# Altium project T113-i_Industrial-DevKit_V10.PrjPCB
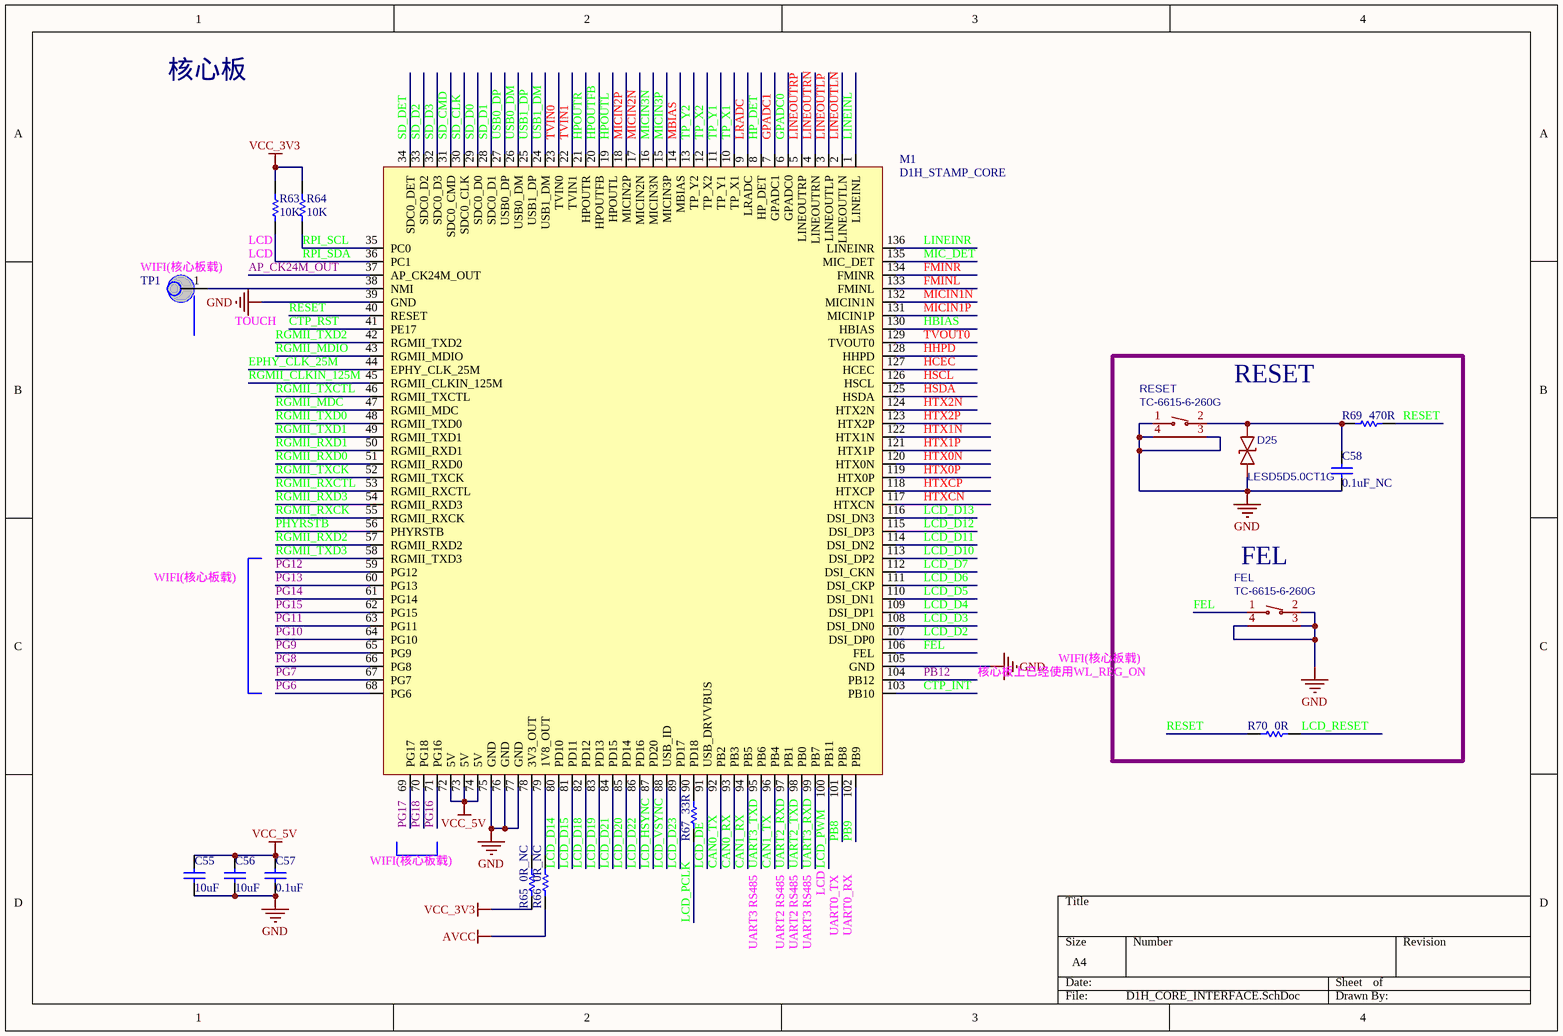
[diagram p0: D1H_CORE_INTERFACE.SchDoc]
6 sheets, 249 parts. Net scope: global (net labels, ports and power ports of the same name join across sheets).
Board file: T113-i_Industrial-DevKit_V10.PcbDoc
Sheets:
  D1H_CORE_INTERFACE.SchDoc
  AUDIO&KEY&EXPAND_IO.SchDoc
  USB&TF.SchDoc
  LCD&PWR.SchDoc
  ETHERNET.SchDoc
  RS485&CAN.SchDoc

## Sheet D1H_CORE_INTERFACE.SchDoc
size A4

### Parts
C55  10uF  [0402]
C56  10uF  [0402]
C57  0.1uF  [0402]
C58  0.1uF_NC  [0402]
D25  LESD5D5.0CT1G  [SOD-523_L1.2-W0.8-LS1.6-BI]
FEL  TC-6615-6-260G  [KEY-TH_TC-6615-6-160G]
M1  D1H_STAMP_CORE  [D1H_STAMP_CORE]
R63  10K  [0402]
R64  10K  [0402]
R65  0R_NC  [1206R]
R66  0R_NC  [1206R]
R67  33R  [0402]
R69  470R  [0402]
R70  0R  [0402]
RESET  TC-6615-6-260G  [KEY-TH_TC-6615-6-160G]
TP1  (no value)  [TP_1MM]

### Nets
AVCC: R66.2
GND: C55.1 C56.1 C57.1 C58.2 D25.1 FEL.2 FEL.3 FEL.4 M1.39(GND) M1.75(GND) M1.76(GND) M1.77(GND) M1.105(GND) RESET.1 RESET.3 RESET.4
VCC_3V3: R63.2 R64.2 R65.2  [project net VCC33_EPHY]
VCC_5V: C55.2 C56.2 C57.2 M1.72(5V) M1.73(5V) M1.74(5V)
AP_CK24M_OUT: M1.37(AP_CK24M_OUT)
CAN0_RX: M1.93(PB3)
CAN0_TX: M1.92(PB2)
CAN1_RX: M1.94(PB5)
CAN1_TX: M1.96(PB4)
CTP_INT: M1.103(PB10)
CTP_RST: M1.41(PE17)
EPHY_CLK_25M: M1.44(EPHY_CLK_25M)
FEL: FEL.1 M1.106(FEL)
FMINL: M1.133(FMINL)
FMINR: M1.134(FMINR)
GPADC0: M1.6(GPADC0)
GPADC1: M1.7(GPADC1)
HBIAS: M1.130(HBIAS)
HCEC: M1.127(HCEC)
HHPD: M1.128(HHPD)
HP_DET: M1.8(HP_DET)
HPOUTFB: M1.20(HPOUTFB)
HPOUTL: M1.19(HPOUTL)
HPOUTR: M1.21(HPOUTR)
HSCL: M1.126(HSCL)
HSDA: M1.125(HSDA)
HTX0N: M1.120(HTX0N)
HTX0P: M1.119(HTX0P)
HTX1N: M1.122(HTX1N)
HTX1P: M1.121(HTX1P)
HTX2N: M1.124(HTX2N)
HTX2P: M1.123(HTX2P)
HTXCN: M1.117(HTXCN)
HTXCP: M1.118(HTXCP)
LCD_D2: M1.107(DSI_DP0)
LCD_D3: M1.108(DSI_DN0)
LCD_D4: M1.109(DSI_DP1)
LCD_D5: M1.110(DSI_DN1)
LCD_D6: M1.111(DSI_CKP)
LCD_D7: M1.112(DSI_CKN)
LCD_D10: M1.113(DSI_DP2)
LCD_D11: M1.114(DSI_DN2)
LCD_D12: M1.115(DSI_DP3)
LCD_D13: M1.116(DSI_DN3)
LCD_D14: M1.80(PD10)
LCD_D15: M1.81(PD11)
LCD_D18: M1.82(PD12)
LCD_D19: M1.83(PD13)
LCD_D20: M1.85(PD14)
LCD_D21: M1.84(PD15)
LCD_D22: M1.86(PD16)
LCD_D23: M1.89(PD17)
LCD_DE: M1.91(USB_DRVVBUS)
LCD_HSYNC: M1.87(PD20)
LCD_PCLK: R67.1
LCD_PWM: M1.100(PB11)
LCD_RESET: R70.2
LCD_VSYNC: M1.88(USB_ID)
LINEINL: M1.1(LINEINL)
LINEINR: M1.136(LINEINR)
LINEOUTLN: M1.2(LINEOUTLN)
LINEOUTLP: M1.3(LINEOUTLP)
LINEOUTRN: M1.4(LINEOUTRN)
LINEOUTRP: M1.5(LINEOUTRP)
LRADC: M1.9(LRADC)
MBIAS: M1.14(MBIAS)
MIC_DET: M1.135(MIC_DET)
MICIN1N: M1.132(MICIN1N)
MICIN1P: M1.131(MICIN1P)
MICIN2N: M1.17(MICIN2N)
MICIN2P: M1.18(MICIN2P)
MICIN3N: M1.16(MICIN3N)
MICIN3P: M1.15(MICIN3P)
PB8: M1.101(PB8)
PB9: M1.102(PB9)
PB12: M1.104(PB12)
PG6: M1.68(PG6)
PG7: M1.67(PG7)
PG8: M1.66(PG8)
PG9: M1.65(PG9)
PG10: M1.64(PG10)
PG11: M1.63(PG11)
PG12: M1.59(PG12)
PG13: M1.60(PG13)
PG14: M1.61(PG14)
PG15: M1.62(PG15)
PG16: M1.71(PG16)
PG17: M1.69(PG17)
PG18: M1.70(PG18)
PHYRSTB: M1.56(PHYRSTB)
RESET: M1.40(RESET) R69.2 R70.1
RGMII_CLKIN_125M: M1.45(RGMII_CLKIN_125M)
RGMII_MDC: M1.47(RGMII_MDC)
RGMII_MDIO: M1.43(RGMII_MDIO)
RGMII_RXCK: M1.55(RGMII_RXCK)
RGMII_RXCTL: M1.53(RGMII_RXCTL)
RGMII_RXD0: M1.51(RGMII_RXD0)
RGMII_RXD1: M1.50(RGMII_RXD1)
RGMII_RXD2: M1.57(RGMII_RXD2)
RGMII_RXD3: M1.54(RGMII_RXD3)
RGMII_TXCK: M1.52(RGMII_TXCK)
RGMII_TXCTL: M1.46(RGMII_TXCTL)
RGMII_TXD0: M1.48(RGMII_TXD0)
RGMII_TXD1: M1.49(RGMII_TXD1)
RGMII_TXD2: M1.42(RGMII_TXD2)
RGMII_TXD3: M1.58(RGMII_TXD3)
RPI_SCL: M1.35(PC0) R64.1
RPI_SDA: M1.36(PC1) R63.1
SD_CLK: M1.30(SDC0_CLK)
SD_CMD: M1.31(SDC0_CMD)
SD_D0: M1.29(SDC0_D0)
SD_D1: M1.28(SDC0_D1)
SD_D2: M1.33(SDC0_D2)
SD_D3: M1.32(SDC0_D3)
SD_DET: M1.34(SDC0_DET)
TP_X1: M1.10(TP_X1)
TP_X2: M1.12(TP_X2)
TP_Y1: M1.11(TP_Y1)
TP_Y2: M1.13(TP_Y2)
TVIN0: M1.23(TVIN0)
TVIN1: M1.22(TVIN1)
TVOUT0: M1.129(TVOUT0)
UART2_RXD: M1.97(PB1)
UART2_TXD: M1.98(PB0)
UART3_RXD: M1.99(PB7)
UART3_TXD: M1.95(PB6)
USB0_DM: M1.26(USB0_DM)
USB0_DP: M1.27(USB0_DP)
USB1_DM: M1.24(USB1_DM)
USB1_DP: M1.25(USB1_DP)
NetC58_1: C58.1 D25.2 R69.1 RESET.2
NetM1_38: M1.38(NMI) TP1.1
NetM1_78: M1.78(3V3_OUT) R65.1
NetM1_79: M1.79(1V8_OUT) R66.1
NetM1_90: M1.90(PD18) R67.2

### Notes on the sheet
- 核心板
- (near R63) LCD
- (near TP1) WIFI(核心板载)
- LCD
- TOUCH
- RESET
- WIFI(核心板载)
- (near FEL) FEL
- 核心板上已经使用WL_REG_ON
- UART3 RS485
- UART2 RS485
- UART0_TX
- UART0_RX

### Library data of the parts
C55-C58 = Cap: Capacitor; PartNumber: CAP100NF
D25 = LESD5D5.0CT1G: BOM_Manufacturer: Leshan Radio; Contributor: LCSC
FEL RESET = TC-6615-6-260G: Contributor: LCSC
R63 R64 R67 R69 R70 = Res1: Resistor; PartNumber: RES2.2K
R65 R66 = Res1: Resistor; PartNumber: RES22R
TP1 = TP

## Sheet AUDIO&KEY&EXPAND_IO.SchDoc
size A4; PageSetup: Record=PageOptions|CenterHorizontal=True|CenterVertical=True|PrintScale=0.50|XCorrection=1.00|YCorrection=1.00|PrintKind=1|BorderSize=5000000|LeftOffset=0|BottomOffset=0|Orientation=2|PaperLength=1000|PaperWidth=1000|Scale=100|PaperSource=7|PrintQuality=-4|MediaType=1|DitherType=10|PaperKind=A4|PrintScaleMode=1
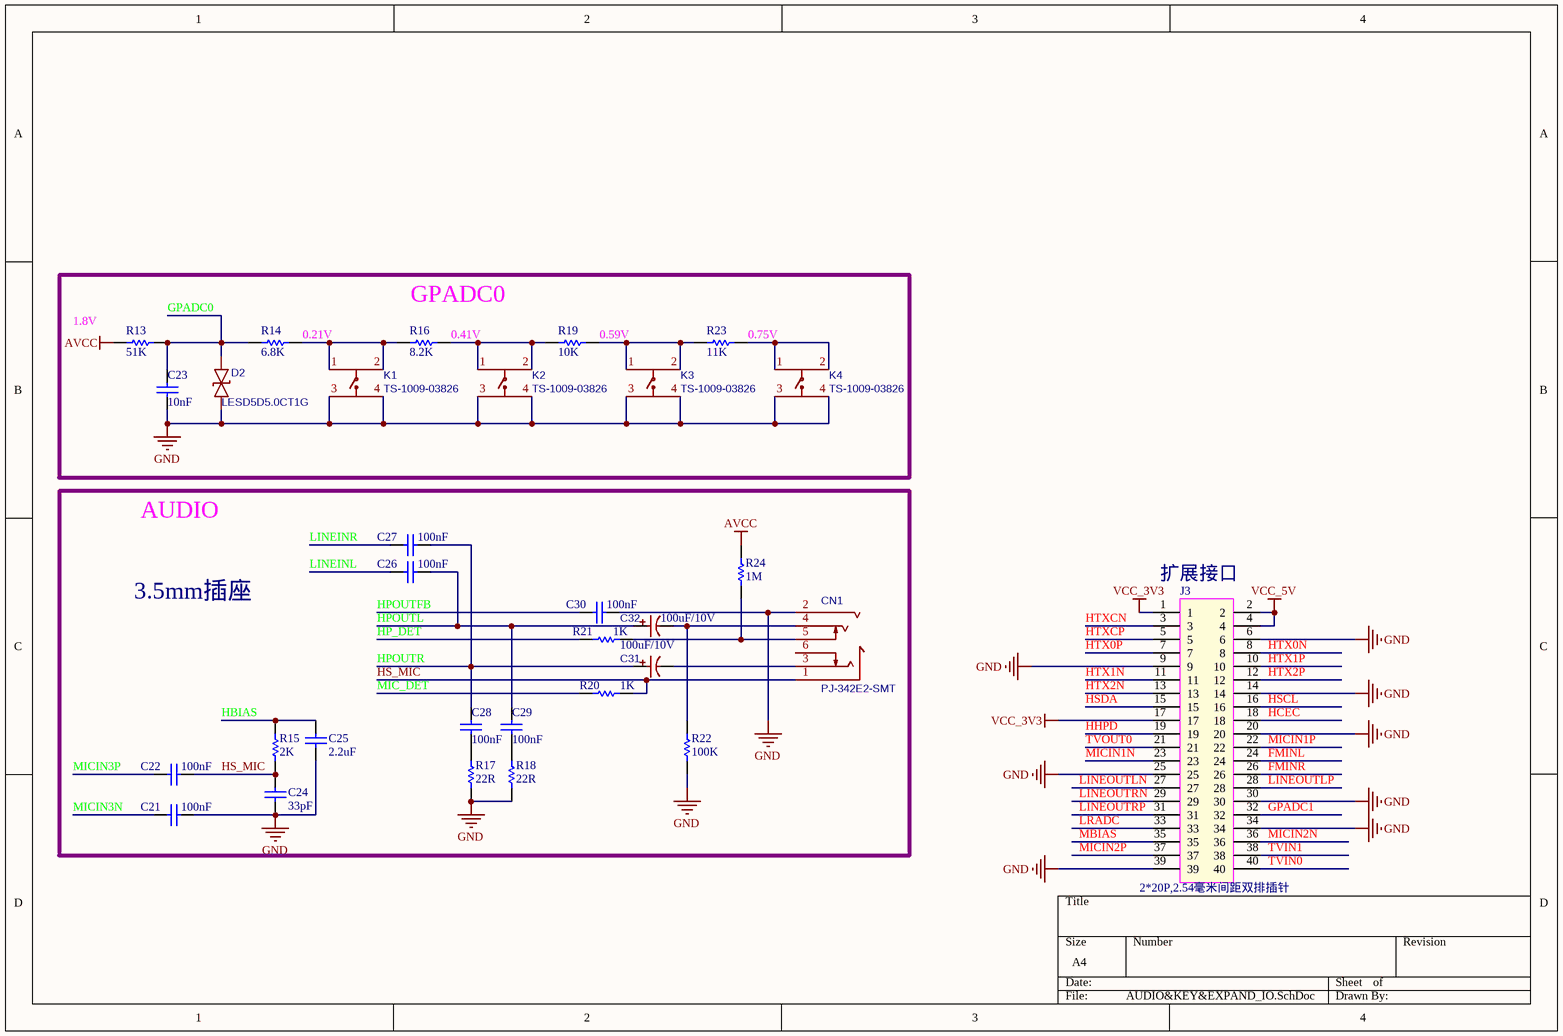
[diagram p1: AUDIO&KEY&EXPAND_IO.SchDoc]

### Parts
C21  100nF  [0402]
C22  100nF  [0402]
C23  10nF  [0402]
C24  33pF  [0402]
C25  2.2uF  [0402]
C26  100nF  [0402]
C27  100nF  [0402]
C28  100nF  [0402]
C29  100nF  [0402]
C30  100nF  [0402]
C31  100uF/10V  [CAP-SMD_CASE_B]
C32  100uF/10V  [CAP-SMD_CASE_B]
CN1  PJ-342E2-SMT  [AUDIO-SMD_PJ-342E2-SMT]
D2  LESD5D5.0CT1G  [SOD-523_L1.2-W0.8-LS1.6-BI]
J3  2*20P,2.54毫米间距双排插针  [HDR-SMD_40P-P2.54-V-M-R2-C20-LS7.5]
K1  TS-1009-03826  [SW-TH_4P-L4.5-W4.5-P3.00-LS5.5]
K2  TS-1009-03826  [SW-TH_4P-L4.5-W4.5-P3.00-LS5.5]
K3  TS-1009-03826  [SW-TH_4P-L4.5-W4.5-P3.00-LS5.5]
K4  TS-1009-03826  [SW-TH_4P-L4.5-W4.5-P3.00-LS5.5]
R13  51K  [0402]
R14  6.8K  [0402]
R15  2K  [0402]
R16  8.2K  [0402]
R17  22R  [0402]
R18  22R  [0402]
R19  10K  [0402]
R20  1K  [0402]
R21  1K  [0402]
R22  100K  [0402]
R23  11K  [0402]
R24  1M  [0402]

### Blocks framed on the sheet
GPADC0: C23 D2 K1-K4 R13 R14 R16 R19 R23

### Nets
AVCC: R13.2 R24.2
GND: C21.1 C23.2 C24.2 C25.2 C30.1 CN1.2 D2.1 J3.6 J3.9 J3.14 J3.20 J3.25 J3.30 J3.34 J3.39 K1.3 K1.4 K2.3 K2.4 K3.3 K3.4 K4.3 K4.4 R17.2 R18.2 R22.1
VCC_3V3: J3.1 J3.17  [project net VCC33_EPHY]
VCC_5V: J3.2 J3.4
FMINL: J3.24
FMINR: J3.26
GPADC0: C23.1 D2.2 R13.1 R14.2
GPADC1: J3.32
HBIAS: C25.1 R15.2
HCEC: J3.18
HHPD: J3.19
HP_DET: R21.2
HPOUTFB: C30.2
HPOUTL: C26.2 C29.1 C32.1
HPOUTR: C27.2 C28.1 C31.1
HS_MIC: C22.1 C24.1 CN1.1 R15.1 R20.1
HSCL: J3.16
HSDA: J3.15
HTX0N: J3.8
HTX0P: J3.7
HTX1N: J3.11
HTX1P: J3.10
HTX2N: J3.13
HTX2P: J3.12
HTXCN: J3.3
HTXCP: J3.5
LINEINL: C26.1
LINEINR: C27.1
LINEOUTLN: J3.27
LINEOUTLP: J3.28
LINEOUTRN: J3.29
LINEOUTRP: J3.31
LRADC: J3.33
MBIAS: J3.35
MIC_DET: R20.2
MICIN1N: J3.23
MICIN1P: J3.22
MICIN2N: J3.36
MICIN2P: J3.37
MICIN3N: C21.2
MICIN3P: C22.2
TVIN0: J3.40
TVIN1: J3.38
TVOUT0: J3.21
NetC28_2: C28.2 R17.1
NetC29_2: C29.2 R18.1
NetC31_2: C31.2 CN1.3
NetC32_2: C32.2 CN1.4 R22.2
NetCN1_5: CN1.5 R21.1 R24.1
NetK1_1: K1.1 K1.2 R14.1 R16.2
NetK2_1: K2.1 K2.2 R16.1 R19.2
NetK3_1: K3.1 K3.2 R19.1 R23.2
NetK4_1: K4.1 K4.2 R23.1

Not connected (* = marked no-connect by the designer): CN1 6

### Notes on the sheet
- (near R13) 1.8V
- (near R14) 0.21V
- (near R16) 0.41V
- (near R19) 0.59V
- (near R23) 0.75V
- AUDIO
- (near J3) 扩展接口
- 3.5mm插座

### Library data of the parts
C21-C30 = Cap: Capacitor; PartNumber: CAP100NF
C31 C32 = 100uF: BOM_Manufacturer: ReliaPro; nameAlias: Capacitance
CN1 = PJ-342E2-SMT: BOM_Manufacturer: XKB Connectivity; Contributor: LCSC
D2 = LESD5D5.0CT1G: as D25 on sheet D1H_CORE_INTERFACE
J3 = IDC40
K1-K4 = KEY_C174049: BOM_Manufacturer: BOOMELE(Boom Precision Elec); Contributor: LCSC; SMT Type: Extend
R13-R24 = Res1: Resistor; PartNumber: RES2.2K

## Sheet USB&TF.SchDoc
size A4
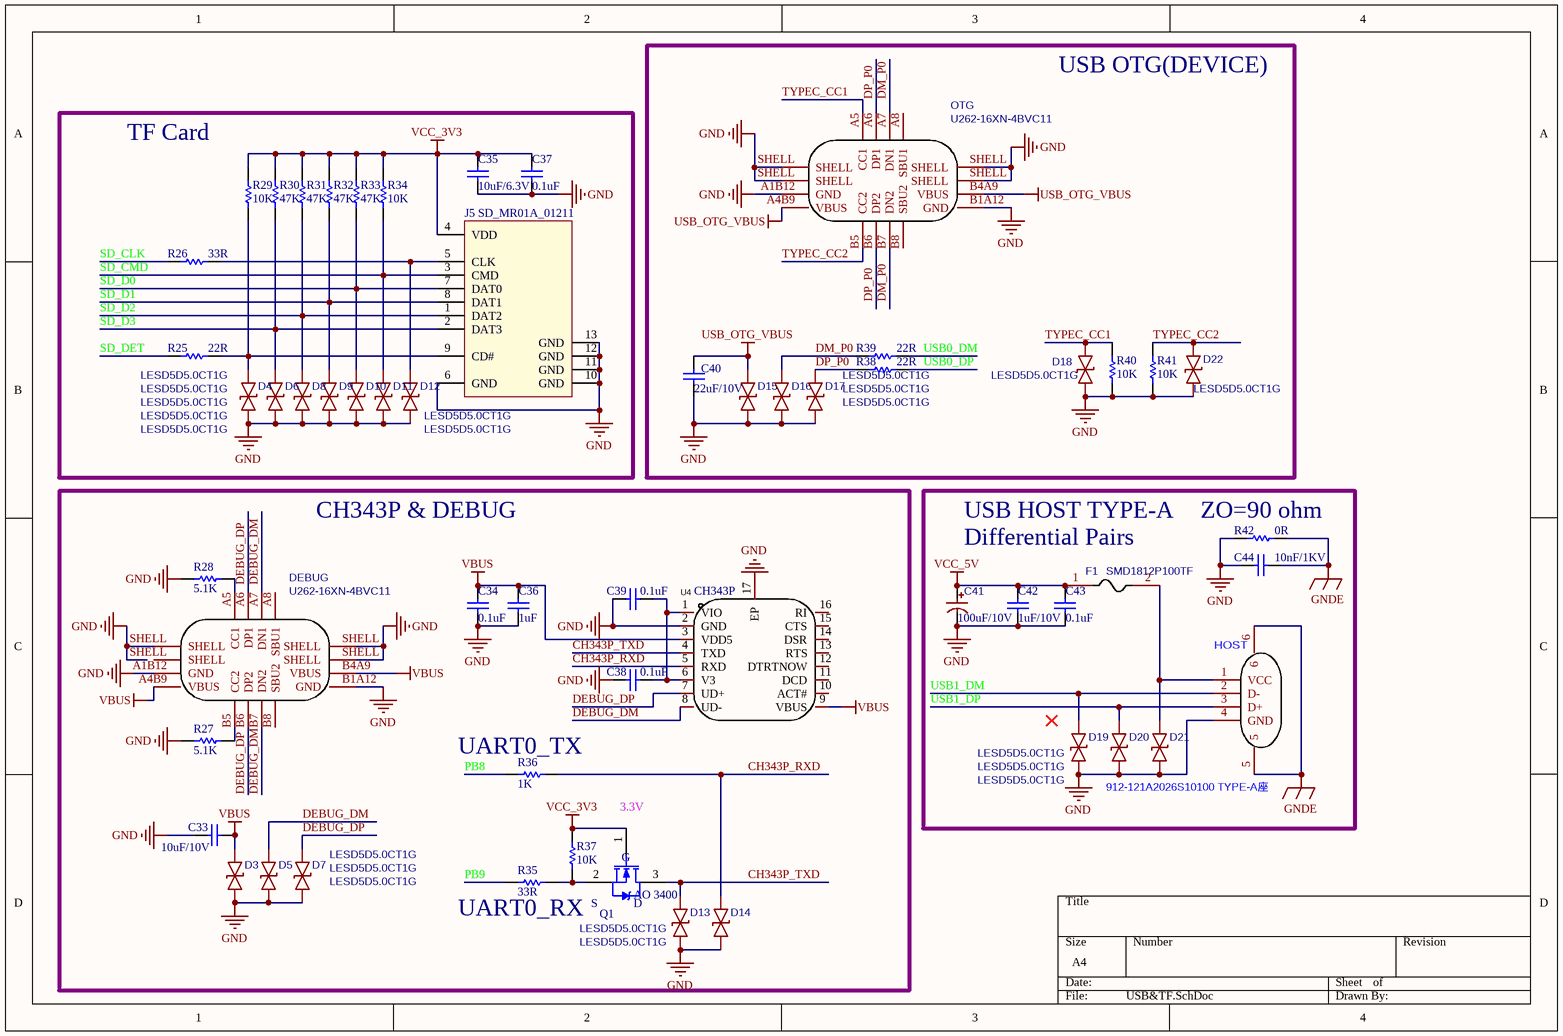
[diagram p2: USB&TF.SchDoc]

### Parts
C33  10uF/10V  [0402]
C34  0.1uF  [0402]
C35  10uF/6.3V  [0402]
C36  1uF  [0402]
C37  0.1uF  [0402]
C38  0.1uF  [0402]
C39  0.1uF  [0402]
C40  22uF/10V  [0603]
C41  100uF/10V  [CAP-SMD_CASE_B]
C42  1uF/10V  [0402]
C43  0.1uF  [0402]
C44  10nF/1KV  [1206C]
D3  LESD5D5.0CT1G  [SOD-523_L1.2-W0.8-LS1.6-BI]
D4  LESD5D5.0CT1G  [SOD-523_L1.2-W0.8-LS1.6-BI]
D5  LESD5D5.0CT1G  [SOD-523_L1.2-W0.8-LS1.6-BI]
D6  LESD5D5.0CT1G  [SOD-523_L1.2-W0.8-LS1.6-BI]
D7  LESD5D5.0CT1G  [SOD-523_L1.2-W0.8-LS1.6-BI]
D8  LESD5D5.0CT1G  [SOD-523_L1.2-W0.8-LS1.6-BI]
D9  LESD5D5.0CT1G  [SOD-523_L1.2-W0.8-LS1.6-BI]
D10  LESD5D5.0CT1G  [SOD-523_L1.2-W0.8-LS1.6-BI]
D11  LESD5D5.0CT1G  [SOD-523_L1.2-W0.8-LS1.6-BI]
D12  LESD5D5.0CT1G  [SOD-523_L1.2-W0.8-LS1.6-BI]
D13  LESD5D5.0CT1G  [SOD-523_L1.2-W0.8-LS1.6-BI]
D14  LESD5D5.0CT1G  [SOD-523_L1.2-W0.8-LS1.6-BI]
D15  LESD5D5.0CT1G  [SOD-523_L1.2-W0.8-LS1.6-BI]
D16  LESD5D5.0CT1G  [SOD-523_L1.2-W0.8-LS1.6-BI]
D17  LESD5D5.0CT1G  [SOD-523_L1.2-W0.8-LS1.6-BI]
D18  LESD5D5.0CT1G  [SOD-523_L1.2-W0.8-LS1.6-BI]
D19  LESD5D5.0CT1G  [SOD-523_L1.2-W0.8-LS1.6-BI]
D20  LESD5D5.0CT1G  [SOD-523_L1.2-W0.8-LS1.6-BI]
D21  LESD5D5.0CT1G  [SOD-523_L1.2-W0.8-LS1.6-BI]
D22  LESD5D5.0CT1G  [SOD-523_L1.2-W0.8-LS1.6-BI]
DEBUG  U262-16XN-4BVC11  [TYPEC-12PIN - duplicate]
F1  SMD1812P100TF  [F1812]
HOST  912-121A2026S10100 TYPE-A座  [USB-A-TH_C42425]
J5  SD_MR01A_01211  [SD-MR01A-01211]
OTG  U262-16XN-4BVC11  [TYPEC-12PIN - duplicate]
Q1  AO 3400  [SOT23]
R25  22R  [0402]
R26  33R  [0402]
R27  5.1K  [0402]
R28  5.1K  [0402]
R29  10K  [0402]
R30  47K  [0402]
R31  47K  [0402]
R32  47K  [0402]
R33  47K  [0402]
R34  10K  [0402]
R35  33R  [0402]
R36  1K  [0402]
R37  10K  [0402]
R38  22R  [0402]
R39  22R  [0402]
R40  10K  [0402]
R41  10K  [0402]
R42  0R  [1206R]
U4  CH343P  [TQFN-16_L3.0-W3.0-P0.50-BL-EP1.7]

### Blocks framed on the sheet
USB OTG(DEVICE): C40 D15-D18 D22 OTG R38-R41
TF Card: C35 C37 D4 D6 D8-D12 J5 R25 R26 R29-R34

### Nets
GND: C33.1 C34.2 C35.2 C36.2 C37.2 C38.1 C39.1 C40.1 C41.2 C42.1 C43.2 C44.1 D3.1 D4.1 D5.1 D6.1 D7.1 D8.1 D9.1 D10.1 D11.1 D12.1 D13.2 D14.2 D15.1 D16.1 D17.1 D18.1 D19.1 D20.1 D21.1 D22.1 DEBUG.A1B12(GND) DEBUG.B1A12(GND) DEBUG.SHELL HOST.4(GND) J5.6(GND) J5.10(GND) J5.11(GND) J5.12(GND) J5.13(GND) OTG.A1B12(GND) OTG.B1A12(GND) OTG.SHELL R27.2 R28.2 R40.1 R41.1 R42.1 U4.2(GND) U4.17(EP)
GNDE: C44.2 HOST.5 HOST.6 R42.2
USB_OTG_VBUS: C40.2 D15.2 OTG.A4B9(VBUS) OTG.B4A9(VBUS)
VBUS: C33.2 C34.1 C36.1 D3.2 DEBUG.A4B9(VBUS) DEBUG.B4A9(VBUS) U4.3(VDD5) U4.9(VBUS)
VCC_3V3: C35.1 C37.1 J5.4(VDD) Q1.1(G) R29.1 R30.1 R31.1 R32.1 R33.1 R34.1 R37.1  [project net VCC33_EPHY]
VCC_5V: C41.1 C42.2 C43.1 F1.1
CH343P_RXD: D14.1 R36.2 U4.5(RXD)
CH343P_TXD: D13.1 Q1.3(D) U4.4(TXD)
DEBUG_DM: D5.2 DEBUG.A7(DN1) DEBUG.B7(DN2) U4.8(UD-)
DEBUG_DP: D7.2 DEBUG.A6(DP1) DEBUG.B6(DP2) U4.7(UD+)
DM_P0: D16.2 OTG.A7(DN1) OTG.B7(DN2) R39.1
DP_P0: D17.2 OTG.A6(DP1) OTG.B6(DP2) R38.1
PB8: R36.1
PB9: R35.1
SD_CLK: R26.2
SD_CMD: D11.2 J5.3(CMD) R34.2
SD_D0: D10.2 J5.7(DAT0) R33.2
SD_D1: D9.2 J5.8(DAT1) R32.2
SD_D2: D8.2 J5.1(DAT2) R31.2
SD_D3: D6.2 J5.2(DAT3) R30.2
SD_DET: R25.2
TYPEC_CC1: D18.2 OTG.A5(CC1) R40.2
TYPEC_CC2: D22.2 OTG.B5(CC2) R41.2
USB0_DM: R39.2
USB0_DP: R38.2
USB1_DM: D19.2 HOST.2(D-)
USB1_DP: D20.2 HOST.3(D+)
NetC38_2: C38.2 C39.2 U4.1(VIO) U4.6(V3)
NetD4_2: D4.2 J5.9(CD#) R25.1 R29.2
NetD12_2: D12.2 J5.5(CLK) R26.1
NetD21_2: D21.2 F1.2 HOST.1(VCC)
NetDEBUG_A5: DEBUG.A5(CC1) R28.1
NetDEBUG_B5: DEBUG.B5(CC2) R27.1
NetQ1_2: Q1.2(S) R35.2 R37.2

Not connected (* = marked no-connect by the designer): DEBUG A8(SBU1) B8(SBU2); OTG A8(SBU1) B8(SBU2); U4 10(ACT#) 11(DCD) 12(DTRTNOW) 13(RTS) 14(DSR) 15(CTS) 16(RI)

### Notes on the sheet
- CH343P & DEBUG
- USB HOST TYPE-A
- (near R42) ZO=90 ohm
- Differential Pairs
- (near R36) UART0_TX
- 3.3V
- (near R35) UART0_RX

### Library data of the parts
C33-C40 C42-C44 = Cap: Capacitor; PartNumber: CAP100NF
C41 = 100uF: as C31 on sheet AUDIO&KEY&EXPAND_IO
D3 D5 D7 D13-D22 = LESD5D5.0CT1G: as D25 on sheet D1H_CORE_INTERFACE
D4 D6 D8-D12 = LESD5D5.0CT1G: BOM_Manufacturer: Leshan Radio; Contributor: LCSC; BOM_Paste Type: expand
DEBUG OTG = U262-16XN-4BVC11: BOM_Manufacturer: XKB Enterprise; Contributor: LCSC
F1 = SMD1812P014TF: BOM_Manufacturer: RUILON
HOST = JTJ-USB-AF-90-10.6X13.1-H5.7-002
Q1 = 1110505011: Note: Pin 2 is electrically connected to pin 4.; 序号: 2666; 存货名称: 场效应管; 规格型号: AO3400,SOT23,N沟道; 主计量单位名称: ֻ; 安全库存: 1346; 旧编码: 010605010; 旧规格型号: N沟道 AO 3400 SOT23
R25-R37 = Res1: Resistor; PartNumber: RES2.2K
R38-R42 = Res1: Resistor; PartNumber: RES22R
U4 = CH343P: Add into BOM: yes

## Sheet LCD&PWR.SchDoc
size A4
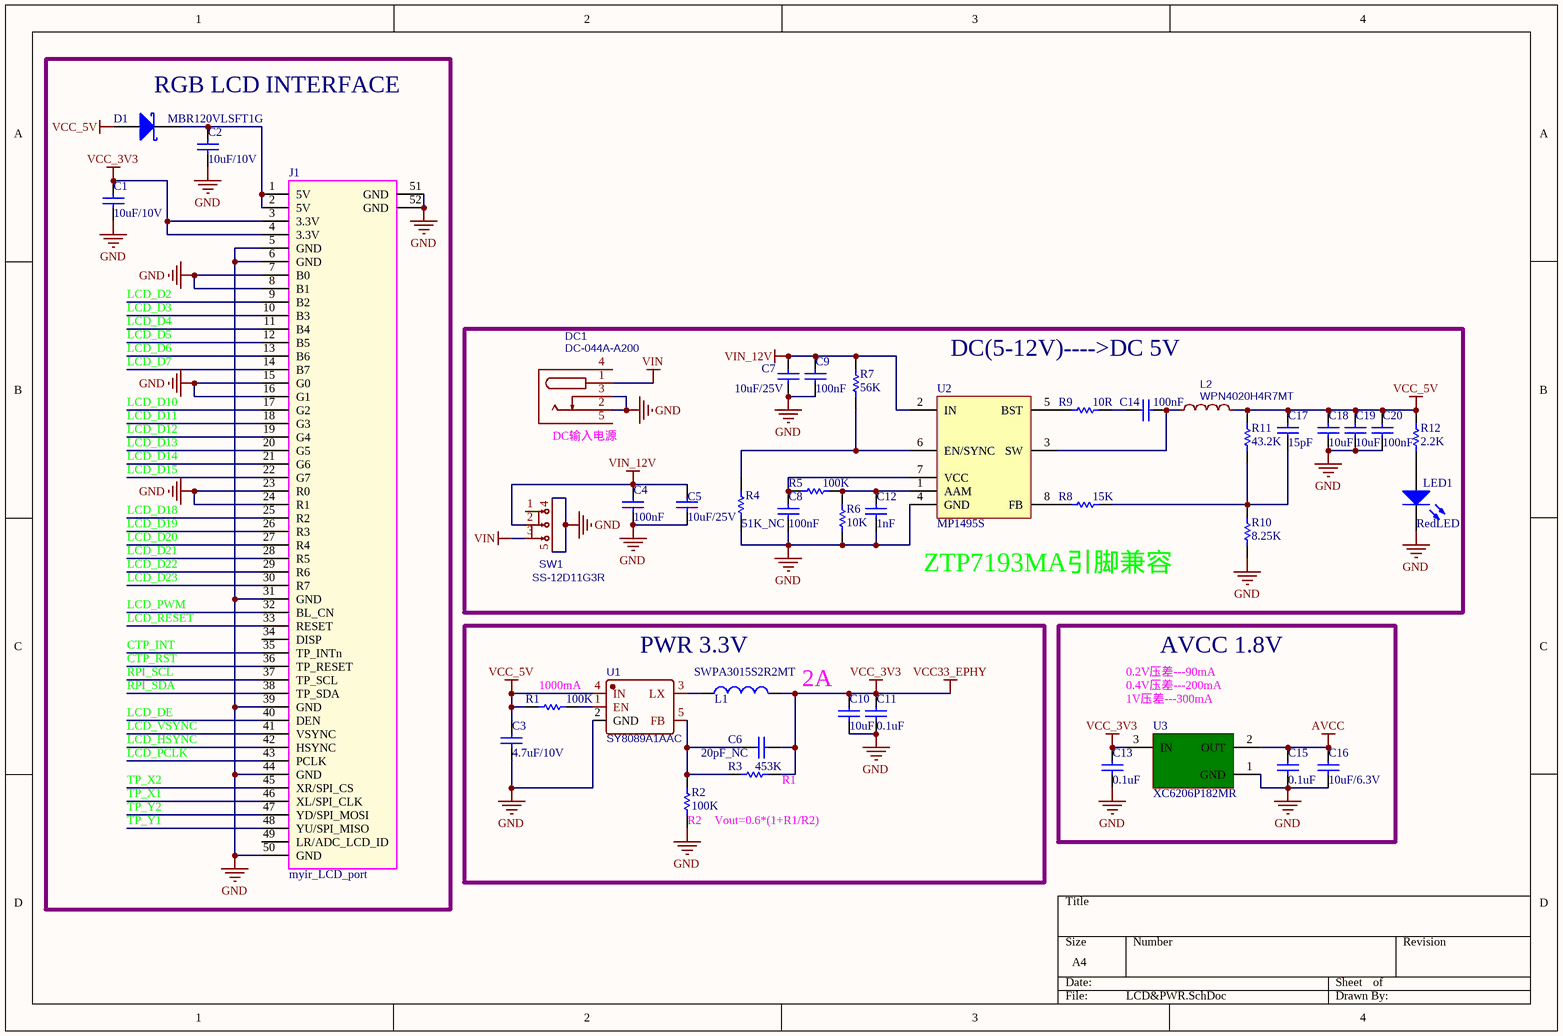
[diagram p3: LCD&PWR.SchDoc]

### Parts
C1  10uF/10V  [0402]
C2  10uF/10V  [0402]
C3  4.7uF/10V  [0402]
C4  100nF  [0402]
C5  10uF/25V  [0603]
C6  20pF_NC  [0402]
C7  10uF/25V  [0603]
C8  100nF  [0402]
C9  100nF  [0402]
C10  10uF  [0402]
C11  0.1uF  [0402]
C12  1nF  [0402]
C13  0.1uF  [0402]
C14  100nF  [0402]
C15  0.1uF  [0402]
C16  10uF/6.3V  [0402]
C17  15pF  [0402]
C18  10uF  [0402]
C19  10uF  [0402]
C20  100nF  [0402]
D1  MBR120VLSFT1G  [SOD-123_L2.8-W1.8-LS3.7-RD]
DC1  DC-044A-A200  [DC-IN-TH_DC-044A-20A]
J1  myir_LCD_port  [FPC-SMD_50P-P0.50_FPC-05FB-50PH20_MIRROR]
L1  SWPA3015S2R2MT  [IND-SMD_L3.0-W3.0]
L2  WPN4020H4R7MT  [IND-SMD_L4.0-W4.0]
LED1  RedLED  [LED0402]
R1  100K  [0402]
R2  100K  [0402]
R3  453K  [0402]
R4  51K_NC  [0402]
R5  100K  [0402]
R6  10K  [0402]
R7  56K  [0402]
R8  15K  [0402]
R9  10R  [0402]
R10  8.25K  [0402]
R11  43.2K  [0402]
R12  2.2K  [0402]
SW1  SS-12D11G3R  [SW-TH_SS-12D11L3]
U1  SY8089A1AAC  [SOT-23-5_L3.0-W1.7-P0.95-LS2.8-BL]
U2  MP1495S  [TSOT-23-8]
U3  XC6206P182MR  [SOT23]

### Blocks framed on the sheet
RGB LCD INTERFACE: C1 C2 D1 J1
ZTP7193MA引脚兼容: C4 C5 C7-C9 C12 C14 C17-C20 DC1 L2 LED1 R4-R12 SW1 U2
AVCC 1.8V: C13 C15 C16 U3

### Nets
AVCC: C15.1 C16.1 U3.2(OUT)
GND: C1.1 C2.1 C3.1 C4.2 C5.2 C7.2 C8.2 C9.2 C10.1 C11.1 C12.2 C13.2 C15.2 C16.2 C18.2 C19.2 C20.2 DC1.2 DC1.3 J1.5(GND) J1.6(GND) J1.7(B0) J1.8(B1) J1.15(G0) J1.16(G1) J1.23(R0) J1.24(R1) J1.31(GND) J1.39(GND) J1.44(GND) J1.50(GND) J1.51(GND) J1.52(GND) LED1.2(K) R2.2 R4.2 R6.2 R10.2 SW1.4 SW1.5 U1.2(GND) U2.4(GND) U3.1(GND)
VCC33_EPHY: C1.2 C6.2 C10.2 C11.2 C13.1 J1.3(3.3V) J1.4(3.3V) L1.2 R3.1 U3.3(IN)  [also labelled VCC_3V3]
VCC_5V: C3.2 C17.1 C18.1 C19.1 C20.1 D1.1(A) L2.2 R1.2 R11.1 R12.2 U1.4(IN)
VIN: DC1.1 SW1.3
VIN_12V: C4.1 C5.1 C7.1 C9.1 R7.1 SW1.2 U2.2(IN)
CTP_INT: J1.35(TP_INTn)
CTP_RST: J1.36(TP_RESET)
LCD_D2: J1.9(B2)
LCD_D3: J1.10(B3)
LCD_D4: J1.11(B4)
LCD_D5: J1.12(B5)
LCD_D6: J1.13(B6)
LCD_D7: J1.14(B7)
LCD_D10: J1.17(G2)
LCD_D11: J1.18(G3)
LCD_D12: J1.19(G4)
LCD_D13: J1.20(G5)
LCD_D14: J1.21(G6)
LCD_D15: J1.22(G7)
LCD_D18: J1.25(R2)
LCD_D19: J1.26(R3)
LCD_D20: J1.27(R4)
LCD_D21: J1.28(R5)
LCD_D22: J1.29(R6)
LCD_D23: J1.30(R7)
LCD_DE: J1.40(DEN)
LCD_HSYNC: J1.42(HSYNC)
LCD_PCLK: J1.43(PCLK)
LCD_PWM: J1.32(BL_CN)
LCD_RESET: J1.33(RESET)
LCD_VSYNC: J1.41(VSYNC)
RPI_SCL: J1.37(TP_SCL)
RPI_SDA: J1.38(TP_SDA)
TP_X1: J1.46(XL/SPI_CLK)
TP_X2: J1.45(XR/SPI_CS)
TP_Y1: J1.48(YU/SPI_MISO)
TP_Y2: J1.47(YD/SPI_MOSI)
NetC2_2: C2.2 D1.2(K) J1.1(5V) J1.2(5V)
NetC6_1: C6.1 R2.1 R3.2 U1.5(FB)
NetC8_1: C8.1 R5.2 U2.7(VCC)
NetC12_1: C12.1 R5.1 R6.1 U2.1(AAM)
NetC14_1: C14.1 R9.1
NetC14_2: C14.2 L2.1 U2.3(SW)
NetC17_2: C17.2 R8.1 R10.1 R11.2
NetL1_1: L1.1 U1.3(LX)
NetLED1_1: LED1.1(A) R12.1
NetR1_1: R1.1 U1.1(EN)
NetR4_1: R4.1 R7.2 U2.6(EN/SYNC)
NetR8_2: R8.2 U2.8(FB)
NetR9_2: R9.2 U2.5(BST)

Not connected (* = marked no-connect by the designer): DC1 4 5; J1 34(DISP) 49(LR/ADC_LCD_ID); SW1 1

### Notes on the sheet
- DC(5-12V)---->DC 5V
- (near DC1) DC输入电源
- PWR 3.3V
- (near R1) 1000mA
- 2A
- 0.2V压差---90mA
- 0.4V压差---200mA
- 1V压差---300mA
- (near R3) R1
- (near R2) R2
- Vout=0.6*(1+R1/R2)

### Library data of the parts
C1-C20 = Cap: Capacitor; PartNumber: CAP100NF
D1 = D Schottky: Schottky Diode
DC1 = DC-044A-A200: Contributor: lcsc
J1 = myir_LCD_port: VALUE: FPC-05FB-50PH20
L1 = Inductor: PartNumber: IND10UH; Code_IEC: 1005
L2 = 4.7uH: BOM_Manufacturer: Sunltech Tech; BOM_Manufacturer Part: SLW6028S4R7MST; nameAlias: Inductance; Contributor: LCSC
LED1 = LED2: Typical RED, GREEN, YELLOW, AMBER GaAs LED
R1-R3 R12 = Res1: Resistor; PartNumber: RES2.2K
R4-R11 = Res1: Resistor; PartNumber: RES22R
SW1 = SS-12D11G3R: BOM_Manufacturer: XKB Connectivity; Contributor: LCSC
U1 = SY8089A1AAC: BOM_Manufacturer: Silergy Corp; Contributor: LCSC
U3 = XC6206

## Sheet ETHERNET.SchDoc
size A3
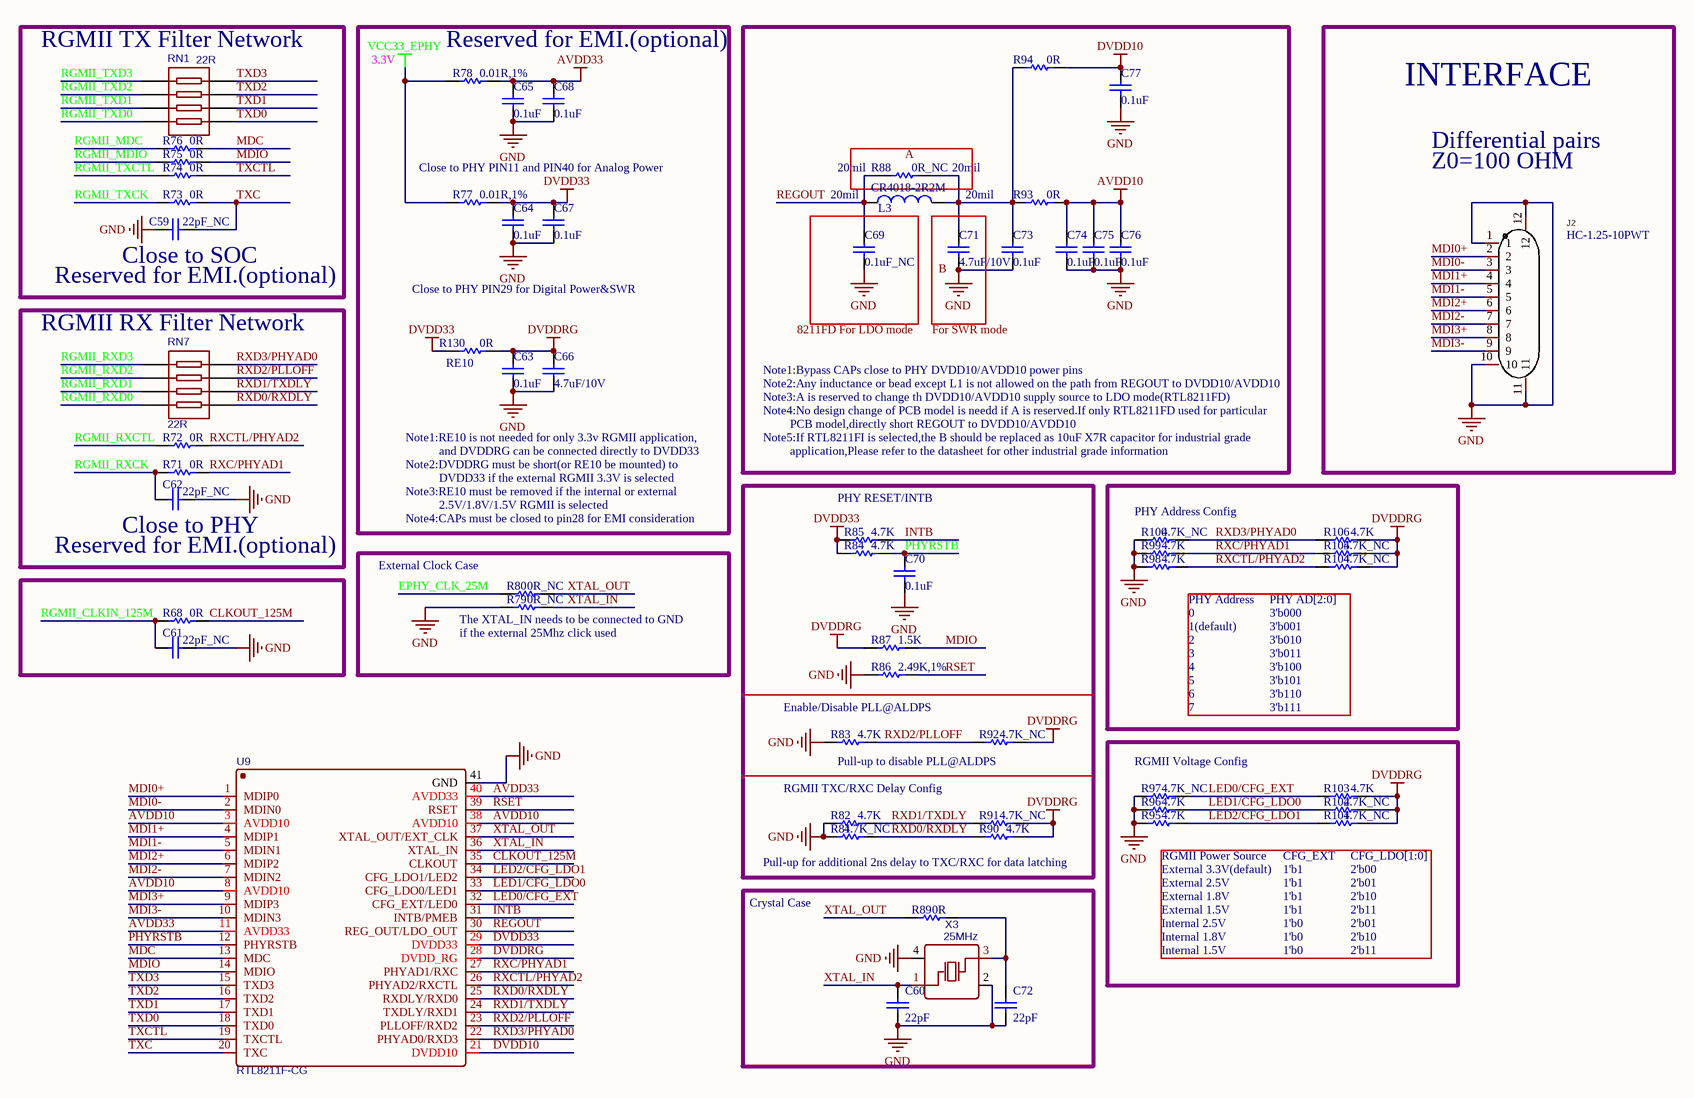
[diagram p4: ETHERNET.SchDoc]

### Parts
C59  22pF_NC  [0402]
C60  22pF  [0402]
C61  22pF_NC  [0402]
C62  22pF_NC  [0402]
C63  0.1uF  [0402]
C64  0.1uF  [0402]
C65  0.1uF  [0402]
C66  4.7uF/10V  [0603]
C67  0.1uF  [0402]
C68  0.1uF  [0402]
C69  0.1uF_NC  [0402]
C70  0.1uF  [0402]
C71  4.7uF/10V  [0603]
C72  22pF  [0402]
C73  0.1uF  [0402]
C74  0.1uF  [0402]
C75  0.1uF  [0402]
C76  0.1uF  [0402]
C77  0.1uF  [0402]
J2  HC-1.25-10PWT  [CONN-SMD_10P-P1.25_HCTL_HC-1.25-10PWT]
L3  CR4018-2R2M  [IND-SMD_L4.0-W4.0]
R68  0R  [0402]
R71  0R  [0402]
R72  0R  [0402]
R73  0R  [0402]
R74  0R  [0402]
R75  0R  [0402]
R76  0R  [0402]
R77  0.01R,1%  [0603]
R78  0.01R,1%  [0603]
R79  0R_NC  [0402]
R80  0R_NC  [0402]
R81  4.7K_NC  [0402]
R82  4.7K  [0402]
R83  4.7K  [0402]
R84  4.7K  [0402]
R85  4.7K  [0402]
R86  2.49K,1%  [0402]
R87  1.5K  [0402]
R88  0R_NC  [0603]
R89  0R  [0402]
R90  4.7K  [0402]
R91  4.7K_NC  [0402]
R92  4.7K_NC  [0402]
R93  0R  [0603]
R94  0R  [0603]
R95  4.7K  [0402]
R96  4.7K  [0402]
R97  4.7K_NC  [0402]
R98  4.7K  [0402]
R99  4.7K  [0402]
R100  4.7K_NC  [0402]
R101  4.7K_NC  [0402]
R102  4.7K_NC  [0402]
R103  4.7K  [0402]
R104  4.7K_NC  [0402]
R105  4.7K_NC  [0402]
R106  4.7K  [0402]
R130  0R  [0402]
RN1  22R  [RES-ARRAY-SMD_0402-8P-L2.0-W1.0-BL]
RN7  22R  [RES-ARRAY-SMD_0402-8P-L2.0-W1.0-BL]
U9  RTL8211F-CG  [WQFN-40_L5.0-W5.0-P0.4-BL-EP]
X3  25MHz  [OSC-SMD_4P-L2.5-W2.0-BL]

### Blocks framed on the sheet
Reserved for EMI.(optional): C63-C68 R77 R78 R130
INTERFACE: J2
20mil: C69
Crystal Case: C60 C72 R89 X3

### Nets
AVDD10: C74.1 C75.1 C76.1 R93.1 U9.3(AVDD10) U9.8(AVDD10) U9.38(AVDD10)
AVDD33: C65.1 C68.1 R78.1 U9.11(AVDD33) U9.40(AVDD33)
DVDD10: C77.1 R94.1 U9.21(DVDD10)
DVDD33: C64.1 C67.1 R77.1 R84.2 R85.2 R130.2 U9.29(DVDD33)
DVDDRG: C63.1 C66.1 R87.2 R90.1 R91.1 R92.1 R101.1 R102.1 R103.1 R104.1 R105.1 R106.1 R130.1 U9.28(DVDD_RG)
GND: C59.1 C60.2 C61.2 C62.2 C63.2 C64.2 C65.2 C66.2 C67.2 C68.2 C69.2 C70.2 C71.2 C72.2 C73.2 C74.2 C75.2 C76.2 C77.2 J2.1 J2.10 J2.11 J2.12 R79.2 R81.2 R82.2 R83.2 R86.2 R95.2 R96.2 R97.2 R98.2 R99.2 R100.2 U9.41(GND) X3.2(GND) X3.4(GND)
VCC33_EPHY: R77.2 R78.2
CLKOUT_125M: R68.1 U9.35(CLKOUT)
EPHY_CLK_25M: R80.2
INTB: R85.1 U9.31(INTB/PMEB)
LED0/CFG_EXT: R97.1 R103.2 U9.32(CFG_EXT/LED0)
LED1/CFG_LDO0: R96.1 R102.2 U9.33(CFG_LDO0/LED1)
LED2/CFG_LDO1: R95.1 R101.2 U9.34(CFG_LDO1/LED2)
MDC: R76.1 U9.13(MDC)
MDI0+: J2.2 U9.1(MDIP0)
MDI0-: J2.3 U9.2(MDIN0)
MDI1+: J2.4 U9.4(MDIP1)
MDI1-: J2.5 U9.5(MDIN1)
MDI2+: J2.6 U9.6(MDIP2)
MDI2-: J2.7 U9.7(MDIN2)
MDI3+: J2.8 U9.9(MDIP3)
MDI3-: J2.9 U9.10(MDIN3)
MDIO: R75.1 R87.1 U9.14(MDIO)
PHYRSTB: C70.1 R84.1 U9.12(PHYRSTB)
REGOUT: C69.1 L3.1 R88.2 U9.30(REG_OUT/LDO_OUT)
RGMII_CLKIN_125M: C61.1 R68.2
RGMII_MDC: R76.2
RGMII_MDIO: R75.2
RGMII_RXCK: C62.1 R71.2
RGMII_RXCTL: R72.2
RGMII_RXD0: RN7.5
RGMII_RXD1: RN7.6
RGMII_RXD2: RN7.7
RGMII_RXD3: RN7.8
RGMII_TXCK: R73.2
RGMII_TXCTL: R74.2
RGMII_TXD0: RN1.5
RGMII_TXD1: RN1.6
RGMII_TXD2: RN1.7
RGMII_TXD3: RN1.8
RSET: R86.1 U9.39(RSET)
RXC/PHYAD1: R71.1 R99.1 R105.2 U9.27(PHYAD1/RXC)
RXCTL/PHYAD2: R72.1 R98.1 R104.2 U9.26(PHYAD2/RXCTL)
RXD0/RXDLY: R81.1 R90.2 RN7.4 U9.25(RXDLY/RXD0)
RXD1/TXDLY: R82.1 R91.2 RN7.3 U9.24(TXDLY/RXD1)
RXD2/PLLOFF: R83.1 R92.2 RN7.2 U9.23(PLLOFF/RXD2)
RXD3/PHYAD0: R100.1 R106.2 RN7.1 U9.22(PHYAD0/RXD3)
TXC: C59.2 R73.1 U9.20(TXC)
TXCTL: R74.1 U9.19(TXCTL)
TXD0: RN1.4 U9.18(TXD0)
TXD1: RN1.3 U9.17(TXD1)
TXD2: RN1.2 U9.16(TXD2)
TXD3: RN1.1 U9.15(TXD3)
XTAL_IN: C60.1 R79.1 U9.36(XTAL_IN) X3.1(OSC1)
XTAL_OUT: R80.1 R89.2 U9.37(XTAL_OUT/EXT_CLK)
NetC71_1: C71.1 C73.1 L3.2 R88.1 R93.2 R94.2
NetC72_1: C72.1 R89.1 X3.3(OSC2)

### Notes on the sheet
- (near RN1) RGMII TX Filter Network
- 3.3V
- Differential pairs
- Close to PHY PIN11 and PIN40 for Analog Power
- 20mil
- (near R88) A
- Z0=100 OHM
- (near C59) Reserved for EMI.(optional)
- (near C59) Close to SOC
- (near C71) B
- (near RN7) RGMII RX Filter Network
- Close to PHY PIN29 for Digital Power&SWR
- 8211FD For LDO mode
- For SWR mode
- (near R130) RE10
- Note1:Bypass CAPs close to PHY DVDD10/AVDD10 power pins
- Note2:Any inductance or bead except L1 is not allowed on the path from REGOUT to DVDD10/AVDD10
- Note3:A is reserved to change th DVDD10/AVDD10 supply source to LDO mode(RTL8211FD)
- Note4:No design change of PCB model is needd if A is reserved.If only RTL8211FD used for particular
- Note1:RE10 is not needed for only 3.3v RGMII application,
- Note2:DVDDRG must be short(or RE10 be mounted) to
- and DVDDRG can be connected directly to DVDD33
- DVDD33 if the external RGMII 3.3V is selected
- Note5:If RTL8211FI is selected,the B should be replaced as 10uF X7R capacitor for industrial grade
- PCB model,directly short REGOUT to DVDD10/AVDD10
- application,Please refer to the datasheet for other industrial grade information
- (near C62) Reserved for EMI.(optional)
- (near C62) Close to PHY
- Note3:RE10 must be removed if the internal or external
- Note4:CAPs must be closed to pin28 for EMI consideration
- 2.5V/1.8V/1.5V RGMII is selected
- PHY RESET/INTB
- PHY Address Config
- External Clock Case
- PHY Address
- 0
- PHY AD[2:0]
- 3'b000
- (near R79) The XTAL_IN needs to be connected to GND
- if the external 25Mhz click used
- 1(default)
- 2
- 3
- 4
- 5
- 3'b001
- 3'b010
- 3'b011
- 3'b100
- 3'b101
- Enable/Disable PLL@ALDPS
- 6
- 7
- 3'b110
- 3'b111
- RGMII TXC/RXC Delay Config
- Pull-up to disable PLL@ALDPS
- RGMII Voltage Config
- Pull-up for additional 2ns delay to TXC/RXC for data latching
- RGMII Power Source
- External 3.3V(default)
- External 2.5V
- CFG_EXT
- 1'b1
- CFG_LDO[1:0]
- 2'b00
- 2'b01
- External 1.8V
- External 1.5V
- Internal 2.5V
- Internal 1.8V
- Internal 1.5V
- 1'b0
- 2'b10
- 2'b11

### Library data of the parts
C59 C61-C71 C73-C77 = Cap: Capacitor; PartNumber: CAP100NF
C60 C72 = Cap: Capacitor; PartNumber: CAP18PF
J2 = HC-1.25-10PWT: Add into BOM: yes; Pitch: 1.25mm; Pins Structure: 1x10P; Number of PINs Per Row: 10; Current Rating (Max): 1A
L3 = Inductor: PartNumber: IND10UH; Code_IEC: 1005
R68 R71-R106 R130 = Res1: Resistor; PartNumber: RES2.2K
RN1 RN7 = RES_ARRAY: BOM_Manufacturer: RALEC; BOM_Manufacturer Part: RTA02-4D220JTH; nameAlias: Resistance (Ohms)
U9 = RTL8211F-CG: BOM_Manufacturer: Realtek Semicon; Contributor: LCSC
X3 = 24MHz: BOM_Manufacturer: JGHC; nameAlias: Frequency; Contributor: LCSC; VALUE: X322525MOB4SI

## Sheet RS485&CAN.SchDoc
size A4
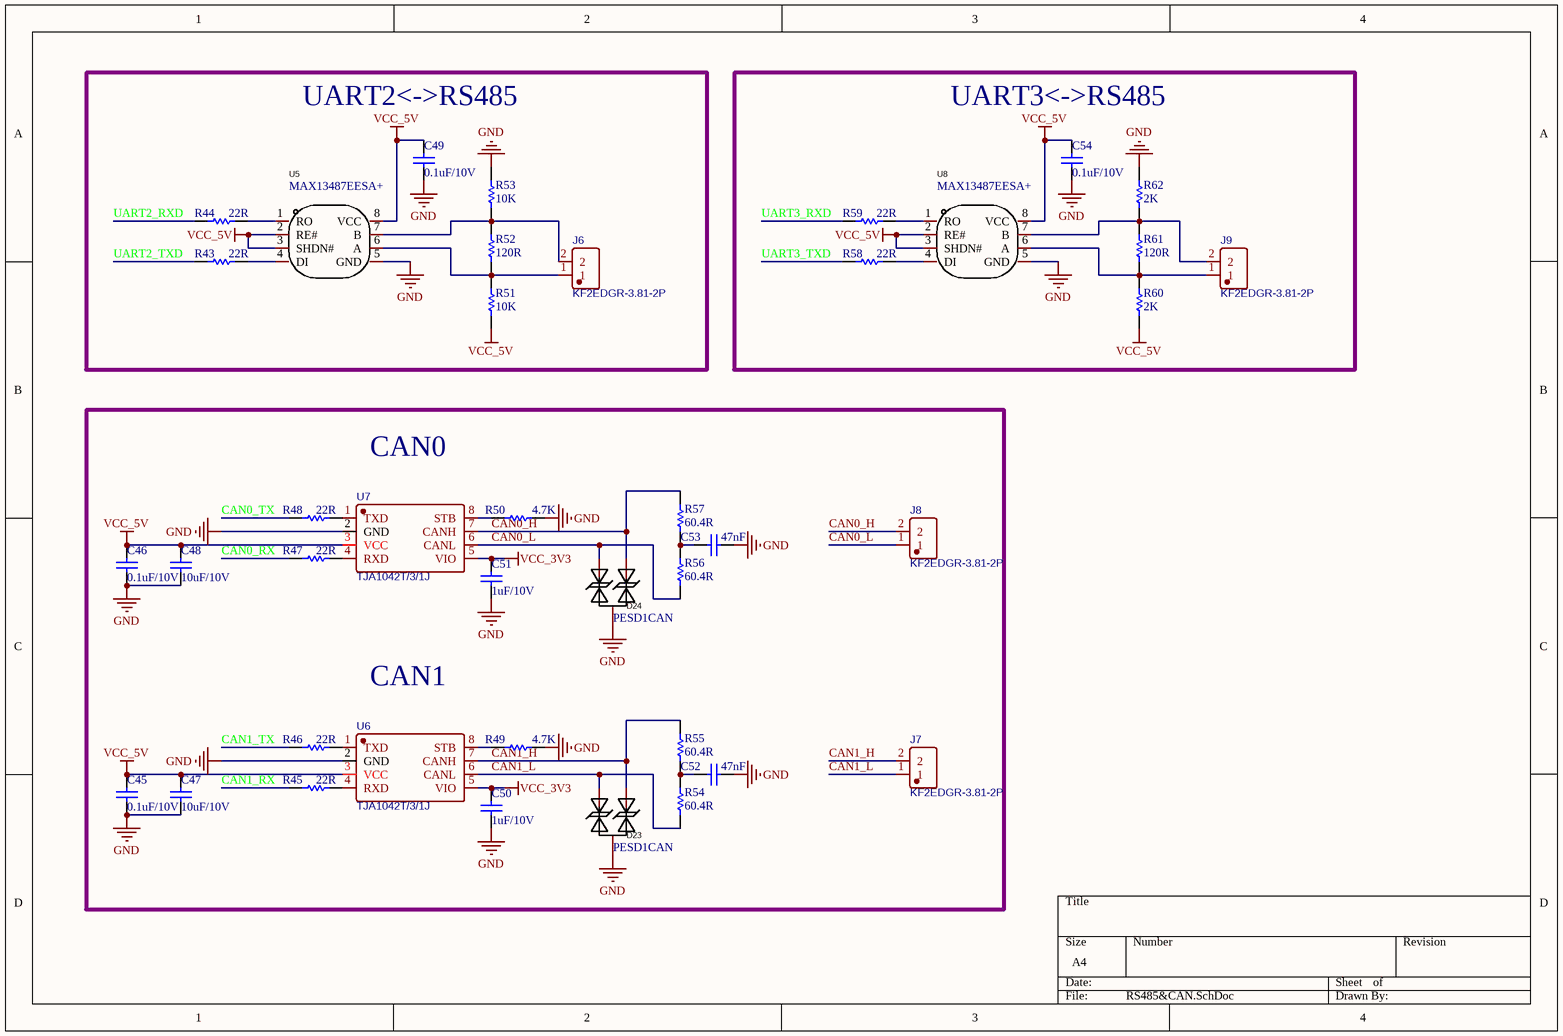
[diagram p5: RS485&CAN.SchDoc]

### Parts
C45  0.1uF/10V  [0402]
C46  0.1uF/10V  [0402]
C47  10uF/10V  [0402]
C48  10uF/10V  [0402]
C49  0.1uF/10V  [0402]
C50  1uF/10V  [0402]
C51  1uF/10V  [0402]
C52  47nF  [0402]
C53  47nF  [0402]
C54  0.1uF/10V  [0402]
D23  PESD1CAN  [SOT-23-3_L2.9-W1.6-P1.90-LS2.8-BR]
D24  PESD1CAN  [SOT-23-3_L2.9-W1.6-P1.90-LS2.8-BR]
J6  KF2EDGR-3.81-2P  [CONN-TH_2P-P3.81_KF2EDGR-3.81-2P]
J7  KF2EDGR-3.81-2P  [CONN-TH_2P-P3.81_KF2EDGR-3.81-2P]
J8  KF2EDGR-3.81-2P  [CONN-TH_2P-P3.81_KF2EDGR-3.81-2P]
J9  KF2EDGR-3.81-2P  [CONN-TH_2P-P3.81_KF2EDGR-3.81-2P]
R43  22R  [0402]
R44  22R  [0402]
R45  22R  [0402]
R46  22R  [0402]
R47  22R  [0402]
R48  22R  [0402]
R49  4.7K  [0402]
R50  4.7K  [0402]
R51  10K  [0402]
R52  120R  [0603]
R53  10K  [0402]
R54  60.4R  [0402]
R55  60.4R  [0402]
R56  60.4R  [0402]
R57  60.4R  [0402]
R58  22R  [0402]
R59  22R  [0402]
R60  2K  [0402]
R61  120R  [0603]
R62  2K  [0402]
U5  MAX13487EESA+  [SOIC-8_L4.9-W3.9-P1.27-LS6.0-BL]
U6  TJA1042T/3/1J  [SOIC-8_L4.9-W3.9-P1.27-LS6.0-BL]
U7  TJA1042T/3/1J  [SOIC-8_L4.9-W3.9-P1.27-LS6.0-BL]
U8  MAX13487EESA+  [SOIC-8_L4.9-W3.9-P1.27-LS6.0-BL]

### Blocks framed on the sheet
UART2<->RS485: C49 J6 R43 R44 R51-R53 U5
UART3<->RS485: C54 J9 R58-R62 U8

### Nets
GND: C45.2 C46.2 C47.2 C48.2 C49.1 C50.1 C51.1 C52.2 C53.2 C54.1 D23.3(A) D24.3(A) R49.1 R50.1 R53.2 R62.2 U5.5(GND) U6.2(GND) U7.2(GND) U8.5(GND)
VCC_3V3: C50.2 C51.2 U6.5(VIO) U7.5(VIO)  [project net VCC33_EPHY]
VCC_5V: C45.1 C46.1 C47.1 C48.1 C49.2 C54.2 R51.1 R60.1 U5.2(RE#) U5.3(SHDN#) U5.8(VCC) U6.3(VCC) U7.3(VCC) U8.2(RE#) U8.3(SHDN#) U8.8(VCC)
CAN0_H: D24.1(K) J8.2 R57.2 U7.7(CANH)
CAN0_L: D24.2(K) J8.1 R56.1 U7.6(CANL)
CAN0_RX: R47.2
CAN0_TX: R48.2
CAN1_H: D23.1(K) J7.2 R55.2 U6.7(CANH)
CAN1_L: D23.2(K) J7.1 R54.1 U6.6(CANL)
CAN1_RX: R45.2
CAN1_TX: R46.2
UART2_RXD: R44.1
UART2_TXD: R43.1
UART3_RXD: R59.1
UART3_TXD: R58.1
NetC52_1: C52.1 R54.2 R55.1
NetC53_1: C53.1 R56.2 R57.1
NetJ6_1: J6.1 R51.2 R52.1 U5.6(A)
NetJ6_2: J6.2 R52.2 R53.1 U5.7(B)
NetJ9_1: J9.1 R60.2 R61.1 U8.6(A)
NetJ9_2: J9.2 R61.2 R62.1 U8.7(B)
NetR43_2: R43.2 U5.4(DI)
NetR44_2: R44.2 U5.1(RO)
NetR45_1: R45.1 U6.4(RXD)
NetR46_1: R46.1 U6.1(TXD)
NetR47_1: R47.1 U7.4(RXD)
NetR48_1: R48.1 U7.1(TXD)
NetR49_2: R49.2 U6.8(STB)
NetR50_2: R50.2 U7.8(STB)
NetR58_2: R58.2 U8.4(DI)
NetR59_2: R59.2 U8.1(RO)

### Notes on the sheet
- CAN0
- CAN1

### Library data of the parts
C45-C54 = Cap: Capacitor; PartNumber: CAP100NF
D23 D24 = PESD1CAN_C343993: Add into BOM: yes; Reverse Stand-Off Voltage (Vrwm): 24V; Breakdown Voltage (VBR): 26.7V; Peak Pulse Current(Ipp)@8/20us: 6A; Clamping Voltage@Ipp: 48V
J6-J9 = KF2EDGR-3.5-2P: BOM_Manufacturer: Cixi Kefa Elec; Contributor: LCSC
R43 R44 R58 R59 = Res1: Resistor; PartNumber: RES2.2K
R45-R57 R60-R62 = Res1: Resistor; PartNumber: RES22R
U5 U8 = MAX13487EESA+: Add into BOM: yes; Driver/receiver: 1/1; Data Rate: 500Kbps; Supply Voltage: 4.75V~5.25V
U6 U7 = TJA1042T/3/1J: BOM_Manufacturer: NXP Semicon; Contributor: LCSC

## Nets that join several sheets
AVCC: D1H_CORE_INTERFACE (R66.2), AUDIO&KEY&EXPAND_IO (R13.2 R24.2), LCD&PWR (C15.1 C16.1 U3.2)
GND: D1H_CORE_INTERFACE (16 pins), AUDIO&KEY&EXPAND_IO (26 pins), USB&TF (51 pins), LCD&PWR (43 pins), ETHERNET (37 pins), RS485&CAN (20 pins)
VCC33_EPHY: D1H_CORE_INTERFACE (R63.2 R64.2 R65.2), AUDIO&KEY&EXPAND_IO (J3.1 J3.17), USB&TF (11 pins), LCD&PWR (10 pins), ETHERNET (R77.2 R78.2), RS485&CAN (C50.2 C51.2 U6.5 U7.5)
VCC_5V: D1H_CORE_INTERFACE (6 pins), AUDIO&KEY&EXPAND_IO (J3.2 J3.4), USB&TF (C41.1 C42.2 C43.1 F1.1), LCD&PWR (11 pins), RS485&CAN (16 pins)
CAN0_RX: D1H_CORE_INTERFACE (M1.93), RS485&CAN (R47.2)
CAN0_TX: D1H_CORE_INTERFACE (M1.92), RS485&CAN (R48.2)
CAN1_RX: D1H_CORE_INTERFACE (M1.94), RS485&CAN (R45.2)
CAN1_TX: D1H_CORE_INTERFACE (M1.96), RS485&CAN (R46.2)
CTP_INT: D1H_CORE_INTERFACE (M1.103), LCD&PWR (J1.35)
CTP_RST: D1H_CORE_INTERFACE (M1.41), LCD&PWR (J1.36)
EPHY_CLK_25M: D1H_CORE_INTERFACE (M1.44), ETHERNET (R80.2)
FMINL: D1H_CORE_INTERFACE (M1.133), AUDIO&KEY&EXPAND_IO (J3.24)
FMINR: D1H_CORE_INTERFACE (M1.134), AUDIO&KEY&EXPAND_IO (J3.26)
GPADC0: D1H_CORE_INTERFACE (M1.6), AUDIO&KEY&EXPAND_IO (C23.1 D2.2 R13.1 R14.2)
GPADC1: D1H_CORE_INTERFACE (M1.7), AUDIO&KEY&EXPAND_IO (J3.32)
HBIAS: D1H_CORE_INTERFACE (M1.130), AUDIO&KEY&EXPAND_IO (C25.1 R15.2)
HCEC: D1H_CORE_INTERFACE (M1.127), AUDIO&KEY&EXPAND_IO (J3.18)
HHPD: D1H_CORE_INTERFACE (M1.128), AUDIO&KEY&EXPAND_IO (J3.19)
HP_DET: D1H_CORE_INTERFACE (M1.8), AUDIO&KEY&EXPAND_IO (R21.2)
HPOUTFB: D1H_CORE_INTERFACE (M1.20), AUDIO&KEY&EXPAND_IO (C30.2)
HPOUTL: D1H_CORE_INTERFACE (M1.19), AUDIO&KEY&EXPAND_IO (C26.2 C29.1 C32.1)
HPOUTR: D1H_CORE_INTERFACE (M1.21), AUDIO&KEY&EXPAND_IO (C27.2 C28.1 C31.1)
HSCL: D1H_CORE_INTERFACE (M1.126), AUDIO&KEY&EXPAND_IO (J3.16)
HSDA: D1H_CORE_INTERFACE (M1.125), AUDIO&KEY&EXPAND_IO (J3.15)
HTX0N: D1H_CORE_INTERFACE (M1.120), AUDIO&KEY&EXPAND_IO (J3.8)
HTX0P: D1H_CORE_INTERFACE (M1.119), AUDIO&KEY&EXPAND_IO (J3.7)
HTX1N: D1H_CORE_INTERFACE (M1.122), AUDIO&KEY&EXPAND_IO (J3.11)
HTX1P: D1H_CORE_INTERFACE (M1.121), AUDIO&KEY&EXPAND_IO (J3.10)
HTX2N: D1H_CORE_INTERFACE (M1.124), AUDIO&KEY&EXPAND_IO (J3.13)
HTX2P: D1H_CORE_INTERFACE (M1.123), AUDIO&KEY&EXPAND_IO (J3.12)
HTXCN: D1H_CORE_INTERFACE (M1.117), AUDIO&KEY&EXPAND_IO (J3.3)
HTXCP: D1H_CORE_INTERFACE (M1.118), AUDIO&KEY&EXPAND_IO (J3.5)
LCD_D2: D1H_CORE_INTERFACE (M1.107), LCD&PWR (J1.9)
LCD_D3: D1H_CORE_INTERFACE (M1.108), LCD&PWR (J1.10)
LCD_D4: D1H_CORE_INTERFACE (M1.109), LCD&PWR (J1.11)
LCD_D5: D1H_CORE_INTERFACE (M1.110), LCD&PWR (J1.12)
LCD_D6: D1H_CORE_INTERFACE (M1.111), LCD&PWR (J1.13)
LCD_D7: D1H_CORE_INTERFACE (M1.112), LCD&PWR (J1.14)
LCD_D10: D1H_CORE_INTERFACE (M1.113), LCD&PWR (J1.17)
LCD_D11: D1H_CORE_INTERFACE (M1.114), LCD&PWR (J1.18)
LCD_D12: D1H_CORE_INTERFACE (M1.115), LCD&PWR (J1.19)
LCD_D13: D1H_CORE_INTERFACE (M1.116), LCD&PWR (J1.20)
LCD_D14: D1H_CORE_INTERFACE (M1.80), LCD&PWR (J1.21)
LCD_D15: D1H_CORE_INTERFACE (M1.81), LCD&PWR (J1.22)
LCD_D18: D1H_CORE_INTERFACE (M1.82), LCD&PWR (J1.25)
LCD_D19: D1H_CORE_INTERFACE (M1.83), LCD&PWR (J1.26)
LCD_D20: D1H_CORE_INTERFACE (M1.85), LCD&PWR (J1.27)
LCD_D21: D1H_CORE_INTERFACE (M1.84), LCD&PWR (J1.28)
LCD_D22: D1H_CORE_INTERFACE (M1.86), LCD&PWR (J1.29)
LCD_D23: D1H_CORE_INTERFACE (M1.89), LCD&PWR (J1.30)
LCD_DE: D1H_CORE_INTERFACE (M1.91), LCD&PWR (J1.40)
LCD_HSYNC: D1H_CORE_INTERFACE (M1.87), LCD&PWR (J1.42)
LCD_PCLK: D1H_CORE_INTERFACE (R67.1), LCD&PWR (J1.43)
LCD_PWM: D1H_CORE_INTERFACE (M1.100), LCD&PWR (J1.32)
LCD_RESET: D1H_CORE_INTERFACE (R70.2), LCD&PWR (J1.33)
LCD_VSYNC: D1H_CORE_INTERFACE (M1.88), LCD&PWR (J1.41)
LINEINL: D1H_CORE_INTERFACE (M1.1), AUDIO&KEY&EXPAND_IO (C26.1)
LINEINR: D1H_CORE_INTERFACE (M1.136), AUDIO&KEY&EXPAND_IO (C27.1)
LINEOUTLN: D1H_CORE_INTERFACE (M1.2), AUDIO&KEY&EXPAND_IO (J3.27)
LINEOUTLP: D1H_CORE_INTERFACE (M1.3), AUDIO&KEY&EXPAND_IO (J3.28)
LINEOUTRN: D1H_CORE_INTERFACE (M1.4), AUDIO&KEY&EXPAND_IO (J3.29)
LINEOUTRP: D1H_CORE_INTERFACE (M1.5), AUDIO&KEY&EXPAND_IO (J3.31)
LRADC: D1H_CORE_INTERFACE (M1.9), AUDIO&KEY&EXPAND_IO (J3.33)
MBIAS: D1H_CORE_INTERFACE (M1.14), AUDIO&KEY&EXPAND_IO (J3.35)
MIC_DET: D1H_CORE_INTERFACE (M1.135), AUDIO&KEY&EXPAND_IO (R20.2)
MICIN1N: D1H_CORE_INTERFACE (M1.132), AUDIO&KEY&EXPAND_IO (J3.23)
MICIN1P: D1H_CORE_INTERFACE (M1.131), AUDIO&KEY&EXPAND_IO (J3.22)
MICIN2N: D1H_CORE_INTERFACE (M1.17), AUDIO&KEY&EXPAND_IO (J3.36)
MICIN2P: D1H_CORE_INTERFACE (M1.18), AUDIO&KEY&EXPAND_IO (J3.37)
MICIN3N: D1H_CORE_INTERFACE (M1.16), AUDIO&KEY&EXPAND_IO (C21.2)
MICIN3P: D1H_CORE_INTERFACE (M1.15), AUDIO&KEY&EXPAND_IO (C22.2)
PB8: D1H_CORE_INTERFACE (M1.101), USB&TF (R36.1)
PB9: D1H_CORE_INTERFACE (M1.102), USB&TF (R35.1)
PHYRSTB: D1H_CORE_INTERFACE (M1.56), ETHERNET (C70.1 R84.1 U9.12)
RGMII_CLKIN_125M: D1H_CORE_INTERFACE (M1.45), ETHERNET (C61.1 R68.2)
RGMII_MDC: D1H_CORE_INTERFACE (M1.47), ETHERNET (R76.2)
RGMII_MDIO: D1H_CORE_INTERFACE (M1.43), ETHERNET (R75.2)
RGMII_RXCK: D1H_CORE_INTERFACE (M1.55), ETHERNET (C62.1 R71.2)
RGMII_RXCTL: D1H_CORE_INTERFACE (M1.53), ETHERNET (R72.2)
RGMII_RXD0: D1H_CORE_INTERFACE (M1.51), ETHERNET (RN7.5)
RGMII_RXD1: D1H_CORE_INTERFACE (M1.50), ETHERNET (RN7.6)
RGMII_RXD2: D1H_CORE_INTERFACE (M1.57), ETHERNET (RN7.7)
RGMII_RXD3: D1H_CORE_INTERFACE (M1.54), ETHERNET (RN7.8)
RGMII_TXCK: D1H_CORE_INTERFACE (M1.52), ETHERNET (R73.2)
RGMII_TXCTL: D1H_CORE_INTERFACE (M1.46), ETHERNET (R74.2)
RGMII_TXD0: D1H_CORE_INTERFACE (M1.48), ETHERNET (RN1.5)
RGMII_TXD1: D1H_CORE_INTERFACE (M1.49), ETHERNET (RN1.6)
RGMII_TXD2: D1H_CORE_INTERFACE (M1.42), ETHERNET (RN1.7)
RGMII_TXD3: D1H_CORE_INTERFACE (M1.58), ETHERNET (RN1.8)
RPI_SCL: D1H_CORE_INTERFACE (M1.35 R64.1), LCD&PWR (J1.37)
RPI_SDA: D1H_CORE_INTERFACE (M1.36 R63.1), LCD&PWR (J1.38)
SD_CLK: D1H_CORE_INTERFACE (M1.30), USB&TF (R26.2)
SD_CMD: D1H_CORE_INTERFACE (M1.31), USB&TF (D11.2 J5.3 R34.2)
SD_D0: D1H_CORE_INTERFACE (M1.29), USB&TF (D10.2 J5.7 R33.2)
SD_D1: D1H_CORE_INTERFACE (M1.28), USB&TF (D9.2 J5.8 R32.2)
SD_D2: D1H_CORE_INTERFACE (M1.33), USB&TF (D8.2 J5.1 R31.2)
SD_D3: D1H_CORE_INTERFACE (M1.32), USB&TF (D6.2 J5.2 R30.2)
SD_DET: D1H_CORE_INTERFACE (M1.34), USB&TF (R25.2)
TP_X1: D1H_CORE_INTERFACE (M1.10), LCD&PWR (J1.46)
TP_X2: D1H_CORE_INTERFACE (M1.12), LCD&PWR (J1.45)
TP_Y1: D1H_CORE_INTERFACE (M1.11), LCD&PWR (J1.48)
TP_Y2: D1H_CORE_INTERFACE (M1.13), LCD&PWR (J1.47)
TVIN0: D1H_CORE_INTERFACE (M1.23), AUDIO&KEY&EXPAND_IO (J3.40)
TVIN1: D1H_CORE_INTERFACE (M1.22), AUDIO&KEY&EXPAND_IO (J3.38)
TVOUT0: D1H_CORE_INTERFACE (M1.129), AUDIO&KEY&EXPAND_IO (J3.21)
UART2_RXD: D1H_CORE_INTERFACE (M1.97), RS485&CAN (R44.1)
UART2_TXD: D1H_CORE_INTERFACE (M1.98), RS485&CAN (R43.1)
UART3_RXD: D1H_CORE_INTERFACE (M1.99), RS485&CAN (R59.1)
UART3_TXD: D1H_CORE_INTERFACE (M1.95), RS485&CAN (R58.1)
USB0_DM: D1H_CORE_INTERFACE (M1.26), USB&TF (R39.2)
USB0_DP: D1H_CORE_INTERFACE (M1.27), USB&TF (R38.2)
USB1_DM: D1H_CORE_INTERFACE (M1.24), USB&TF (D19.2 HOST.2)
USB1_DP: D1H_CORE_INTERFACE (M1.25), USB&TF (D20.2 HOST.3)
